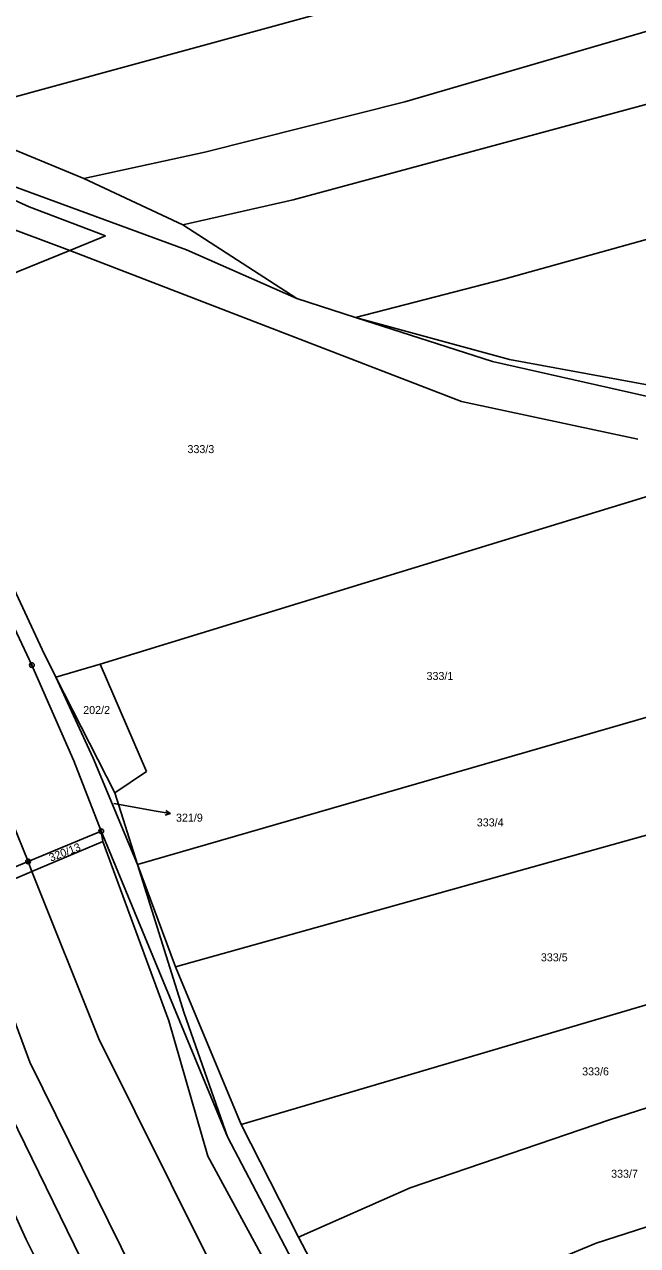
# Model space of a CAD drawing. Extents: x -762263 to -760336, y -1154405 to -1152076.
# Drawn here: x -761122 to -760991.9, y -1152889.5 to -1152630.1 of the extents above; entities that cross this region are included whole.
import ezdxf

# ---------------------------------------------------------------- set-up
doc = ezdxf.new("R2010")
doc.units = 0
for name, color, linetype in [('Vrstva 1', 7, 'Continuous'), ('Vrstva 16', 7, 'Continuous'), ('Vrstva 18', 7, 'Continuous'), ('Vrstva 24', 7, 'Continuous'), ('Vrstva 6', 7, 'Continuous')]:
    doc.layers.add(name, color=color, linetype=linetype)

msp = doc.modelspace()

# ---------------------------------------------------------------- linework, layer by layer
at = {"layer": 'Vrstva 1'}
for p, q in [((-761150.56, -1152654.88), (-761087.62, -1152677.96)), ((-761128.74, -1152672.01), (-761112.42, -1152678.12)), ((-761112.42, -1152678.12), (-761150.81, -1152693.69)), ((-761029.24, -1152710.24), (-761112.42, -1152678.12)), ((-761087.62, -1152677.96), (-761064.2, -1152688.34)), ((-761064.2, -1152688.34), (-761051.79, -1152692.34)), ((-761120.45, -1152766.21), (-761154.94, -1152693.06)), ((-761051.79, -1152692.34), (-761022.68, -1152701.74)), ((-761149.53, -1152695.84), (-761118.24, -1152762.89)), ((-761022.68, -1152701.74), (-760969.06, -1152713.8)), ((-760991.86, -1152718.2), (-761029.24, -1152710.24)), ((-761042.6, -1152746.5), (-760982.8, -1152728.18)), ((-761042.6, -1152746.5), (-761105.93, -1152765.98)), ((-761118.24, -1152762.89), (-761115.4, -1152768.77)), ((-761111.53, -1152786.55), (-761120.45, -1152766.21)), ((-761105.93, -1152765.98), (-761115.4, -1152768.77)), ((-761105.93, -1152765.98), (-761096.12, -1152788.78)), ((-761115.4, -1152768.77), (-761102.86, -1152793.35)), ((-761105.72, -1152801.48), (-761111.53, -1152786.55)), ((-761128.46, -1152790.18), (-761121.27, -1152807.92)), ((-761102.86, -1152793.35), (-761096.12, -1152788.78)), ((-761098.07, -1152808.56), (-761102.86, -1152793.35)), ((-761121.27, -1152807.92), (-761105.72, -1152801.48)), ((-761105.4, -1152803.7), (-761105.72, -1152801.48)), ((-761120.46, -1152810.07), (-761105.4, -1152803.7)), ((-761105.4, -1152803.7), (-761091.41, -1152841.76)), ((-761135.45, -1152813.8), (-761121.27, -1152807.92)), ((-761098.07, -1152808.56), (-761088.1, -1152840.14)), ((-761134.45, -1152815.99), (-761120.46, -1152810.07)), ((-761083.1, -1152870.5), (-761091.41, -1152841.76)), ((-761078.93, -1152866.43), (-761088.1, -1152840.14)), ((-761026.69, -1152966.14), (-761078.93, -1152866.43)), ((-761041.52, -1152947.17), (-761083.1, -1152870.5))]:
    msp.add_line(p, q, dxfattribs=at)
at = {"layer": 'Vrstva 16'}
for p in [(-761103.09, -1152795.62), (-761091.097, -1152797.756)]:
    msp.add_line(p, (-761094.05, -1152797.23), dxfattribs=at)
msp.add_lwpolyline([(-761091.993, -1152797.089), (-761091.097, -1152797.756), (-761092.169, -1152798.073)], dxfattribs=at)
at = {"layer": 'Vrstva 24'}
for centre, radius in [((-761120.45, -1152766.21), 0.5), ((-761120.45, -1152766.21), 0.1), ((-761105.72, -1152801.48), 0.5), ((-761105.72, -1152801.48), 0.1), ((-761121.27, -1152807.92), 0.5), ((-761121.27, -1152807.92), 0.1)]:
    msp.add_circle(centre, radius, dxfattribs=at)
at = {"layer": 'Vrstva 6'}
for p, q in [((-761140.4, -1152649.98), (-761010.32, -1152614.36)), ((-761041.29, -1152646.52), (-760934.96, -1152615.47)), ((-761065, -1152667.4), (-760962.51, -1152639.61)), ((-761083.73, -1152657.21), (-761041.29, -1152646.52)), ((-761140.4, -1152649.98), (-761109.42, -1152662.87)), ((-761109.42, -1152662.87), (-761083.73, -1152657.21)), ((-761109.42, -1152662.87), (-761088.38, -1152672.67)), ((-761132.45, -1152663.66), (-761121.06, -1152668.84)), ((-761088.38, -1152672.67), (-761065, -1152667.4)), ((-761121.06, -1152668.84), (-761104.83, -1152674.99)), ((-761020.26, -1152684.25), (-760967.3, -1152669.41)), ((-761088.38, -1152672.67), (-761064.2, -1152688.34)), ((-761104.83, -1152674.99), (-761112.42, -1152678.12)), ((-761051.79, -1152692.34), (-761020.26, -1152684.25)), ((-761019.09, -1152701.32), (-761051.79, -1152692.34)), ((-760971.71, -1152710.02), (-761019.09, -1152701.32)), ((-761115.4, -1152768.77), (-761107.45, -1152785.96)), ((-761098.07, -1152808.56), (-760972.13, -1152772.12)), ((-761107.45, -1152785.96), (-761098.07, -1152808.56)), ((-761089.99, -1152830.31), (-760942.71, -1152789.09)), ((-761105.72, -1152801.48), (-761078.93, -1152866.43)), ((-761120.46, -1152810.07), (-761121.27, -1152807.92)), ((-761098.07, -1152808.56), (-761089.99, -1152830.31)), ((-761106.27, -1152845.61), (-761120.46, -1152810.07)), ((-761130.45, -1152824.78), (-761120.88, -1152850.57)), ((-761076.01, -1152863.8), (-760952.7, -1152827.35)), ((-761089.99, -1152830.31), (-761076.01, -1152863.8)), ((-761141.67, -1152844.5), (-761121.66, -1152888.19)), ((-761106.27, -1152845.61), (-761083.23, -1152891.86)), ((-761079.69, -1152934.08), (-761120.88, -1152850.57)), ((-760997.88, -1152862.82), (-760960.52, -1152850.8)), ((-761128.94, -1152853.67), (-761079.42, -1152954.68)), ((-761040.13, -1152877.24), (-760997.88, -1152862.82)), ((-761076.01, -1152863.8), (-761063.88, -1152887.7)), ((-761000.71, -1152888.98), (-760936.04, -1152868.11)), ((-761063.88, -1152887.7), (-761040.13, -1152877.24)), ((-761121.66, -1152888.19), (-761093.79, -1152944.26)), ((-761063.88, -1152887.7), (-761051.79, -1152910.8)), ((-761000.71, -1152888.98), (-761026.43, -1152899.68))]:
    msp.add_line(p, q, dxfattribs=at)

# ---------------------------------------------------------------- texts
at = {"layer": 'Vrstva 16'}
msp.add_text('321/9', height=1.7, dxfattribs=at).set_placement((-761089.863, -1152799.46))
at = {"layer": 'Vrstva 18'}
for s, height, p in [('333/3', 1.7, (-761087.433, -1152721.17)), ('333/1', 1.7, (-761036.686, -1152769.36)), ('202/2', 1.7, (-761109.561, -1152776.59)), ('321/9', 0.1, (-761103.281, -1152795.62)), ('333/4', 1.7, (-761026.024, -1152800.47)), ('333/5', 1.7, (-761012.421, -1152829.13)), ('333/6', 1.7, (-761003.664, -1152853.36)), ('333/7', 1.7, (-760997.514, -1152875.1))]:
    msp.add_text(s, height=height, dxfattribs=at).set_placement(p)
msp.add_text('320/13', height=1.7, rotation=21.02755, dxfattribs=at).set_placement((-761116.419, -1152807.983))

doc.saveas('drawing.dxf')
